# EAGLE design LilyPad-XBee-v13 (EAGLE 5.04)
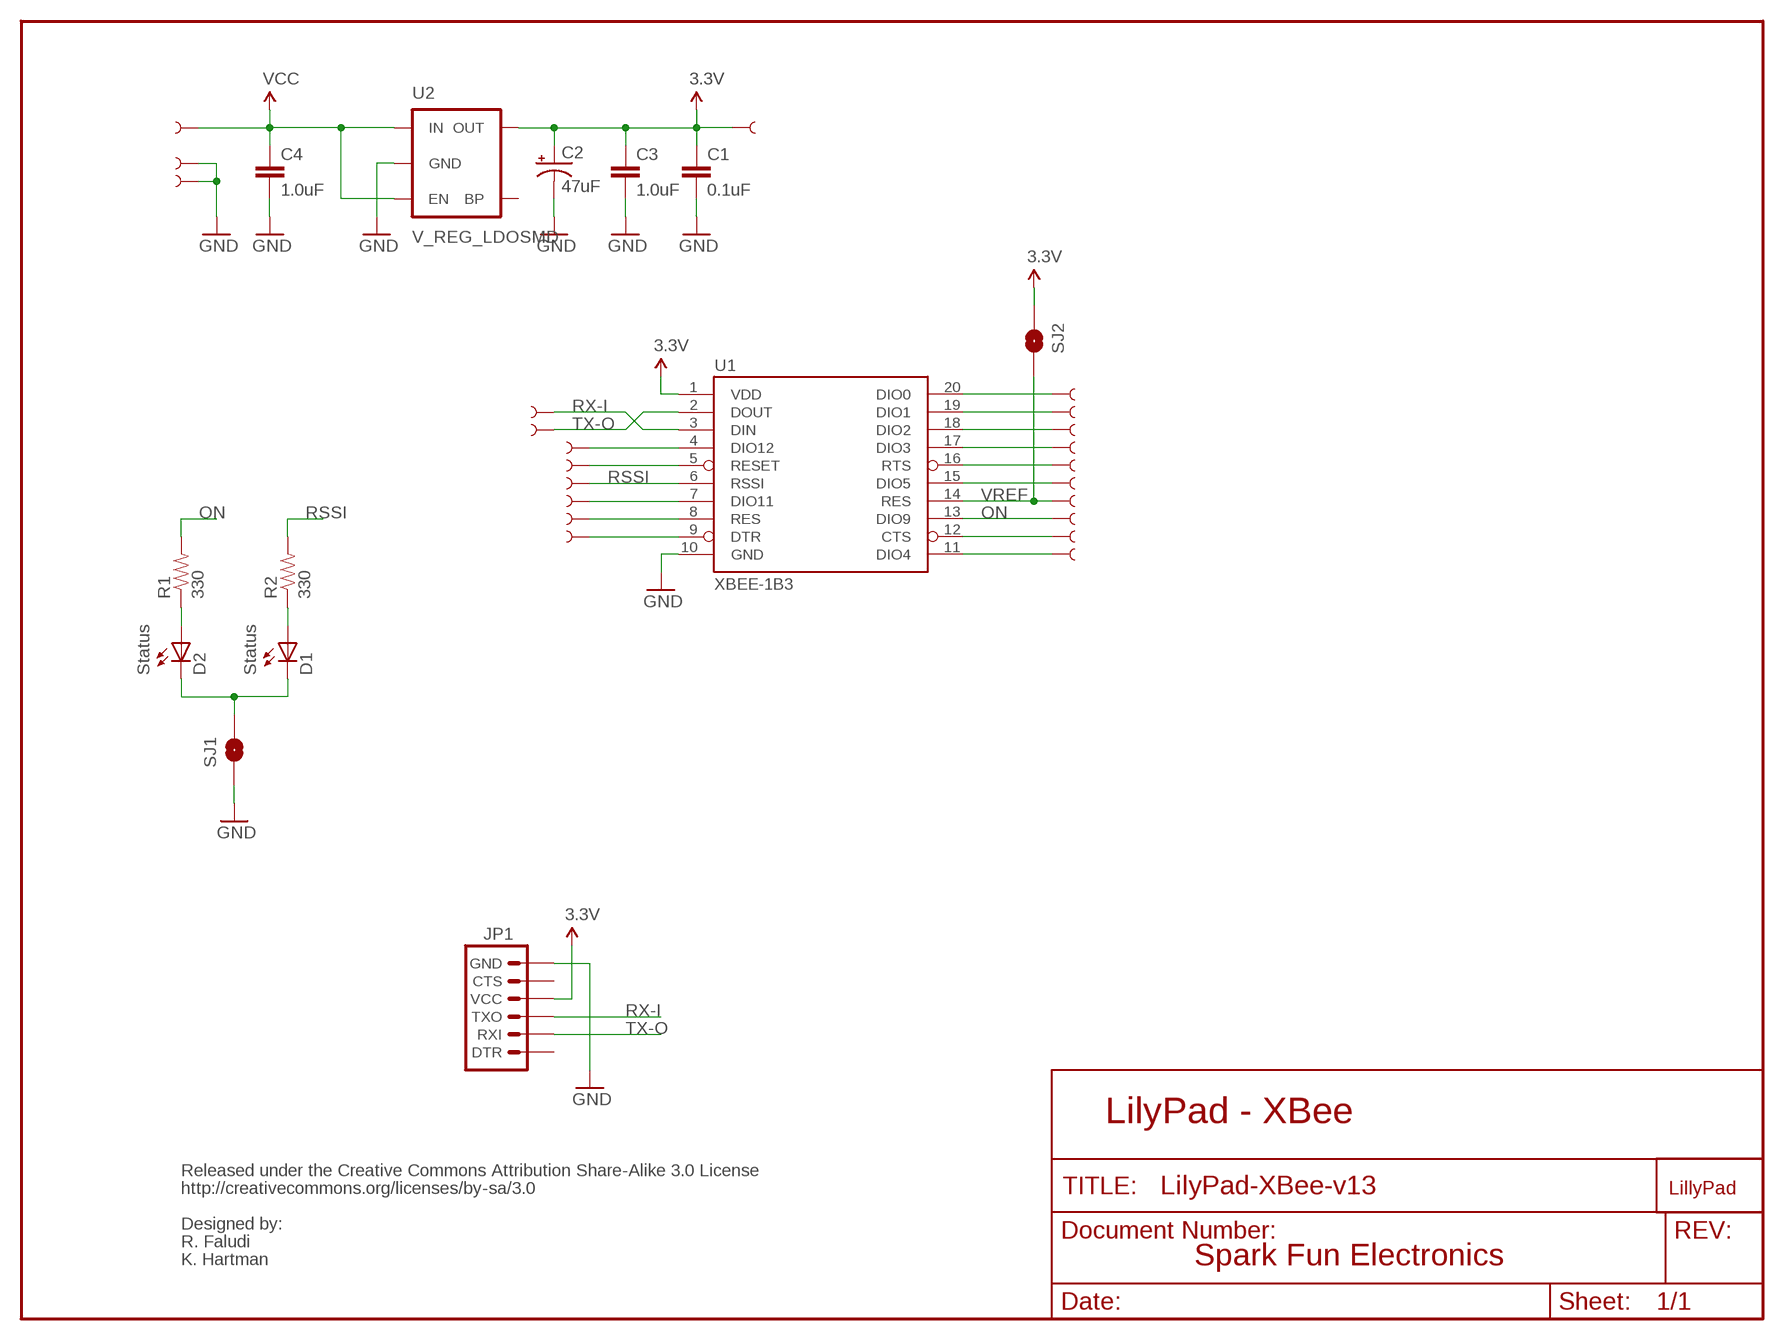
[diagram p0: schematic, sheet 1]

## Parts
C1  0.1uF  CAP0402-CAP  [0402-CAP]
C2  47uF  CAP_POL3528  [EIA3528]
C3  1.0uF  CAP0402-CAP  [0402-CAP]
C4  1.0uF  CAP0402-CAP  [0402-CAP]
D1  Status  LED0603  [LED-0603]
D2  Status  LED0603  [LED-0603]
GND  SEWTAP1  [SEWTAP]
JP1  ARDUINO_SERIAL_PROGRAMPTH  [1X06]
R1  330  RESISTOR0402-RES  [0402-RES]
R2  330  RESISTOR0402-RES  [0402-RES]
SJ1  SOLDERJUMPERNC2  [SJ_2S-NOTRACE]
SJ2  SOLDERJUMPERNC2  [SJ_2S-NOTRACE]
U1  XBEE-1B3  [XBEE-SMD]
U2  V_REG_LDOSMD  [SOT23-5]
U$1  LOGO-LPLP  [LOGO-LILYPAD]
U$4  SEWTAP1  [SEWTAP]
U$30  SEWTAP1  [SEWTAP]
U$31  SEWTAP1  [SEWTAP]
U$32  SEWTAP1  [SEWTAP]
U$33  SEWTAP1  [SEWTAP]
U$34  SEWTAP1  [SEWTAP]
U$35  SEWTAP1  [SEWTAP]
U$36  SEWTAP1  [SEWTAP]
U$37  SEWTAP1  [SEWTAP]
U$38  SEWTAP1  [SEWTAP]
U$39  SEWTAP1  [SEWTAP]
U$40  SEWTAP1  [SEWTAP]
U$41  SEWTAP1  [SEWTAP]
U$42  SEWTAP1  [SEWTAP]
U$43  SEWTAP1  [SEWTAP]
U$44  SEWTAP1  [SEWTAP]
U$45  SEWTAP1  [SEWTAP]
U$46  SEWTAP1  [SEWTAP]
U$47  SEWTAP1  [SEWTAP]
U$48  SEWTAP1  [SEWTAP]
U$51  SEWTAP1  [SEWTAP]

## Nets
3.3V: C1.1 C2.A(+) C3.1 JP1.4(VCC) SJ2.1 U1.1(VDD) U2.5(OUT) U$47.1
GND [VCC]: C1.2 C2.C(-) C3.2 C4.2 JP1.6(GND) SJ1.1 U1.10(GND) U2.2(GND) U$36.1 U$46.1
N$1: D1.A R2.1
N$2: D2.A R1.1
N$3: D1.C D2.C SJ1.2
N$4: U1.4(DIO12) U$43.1
N$5: GND.1 U1.5(RESET)
N$7: U1.7(DIO11) U$42.1
N$8: U1.8(RES) U$41.1
N$9: U1.9(DTR) U$48.1
N$10: U1.15(DIO5) U$4.1
N$11: U1.16(RTS) U$30.1
N$12: U1.11(DIO4) U$37.1
N$13: U1.12(CTS) U$38.1
N$16: U1.17(DIO3) U$31.1
N$17: U1.18(DIO2) U$32.1
N$18: U1.19(DIO1) U$33.1
N$19: U1.20(DIO0) U$34.1
ON: R1.2 U1.13(DIO9) U$39.1
RSSI: R2.2 U1.6(RSSI) U$51.1
RX-I: JP1.3(TXO) U1.3(DIN) U$45.1
TX-O: JP1.2(RXI) U1.2(DOUT) U$44.1
VCC [VCC]: C4.1 U2.1(IN) U2.3(EN) U$35.1
VREF: SJ2.2 U1.14(RES) U$40.1
Unconnected: JP1.1(DTR) JP1.5(CTS) U2.4(BP)

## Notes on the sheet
- LilyPad - XBee
- Released under the Creative Commons Attribution Share-Alike 3.0 License
- http://creativecommons.org/licenses/by-sa/3.0
- Designed by:
- R. Faludi
- K. Hartman | Spark Fun Electronics

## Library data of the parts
C1 C3 C4 = SparkFun:CAP: Capacitor
C2 = SparkFun:CAP_POL: Capacitor Polarized
D1 D2 = SparkFun:LED: LEDs
GND U$4 U$30-U$48 U$51 = LilyPad-Wearables:SEWTAP
JP1 = SparkFun:ARDUINO_SERIAL_PROGRAM
R1 R2 = SparkFun:RESISTOR: Resistor
SJ1 SJ2 = SparkFun:SOLDERJUMPER: Solder Jumper
U1 = SparkFun:XBEE-1
U2 = SparkFun:V_REG_LDO: Voltage Regulator LDO Standard 150mA LDO voltage regulator in SOT-23 layout. Micrel part MIC5205. BP (by-pass) pin is used to lower output noise with 470pF cap.
U$1 = LilyPad-Wearables:LOGO-LP

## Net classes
0 Default: width 0.203 mm
1 VCC: width 0.305 mm

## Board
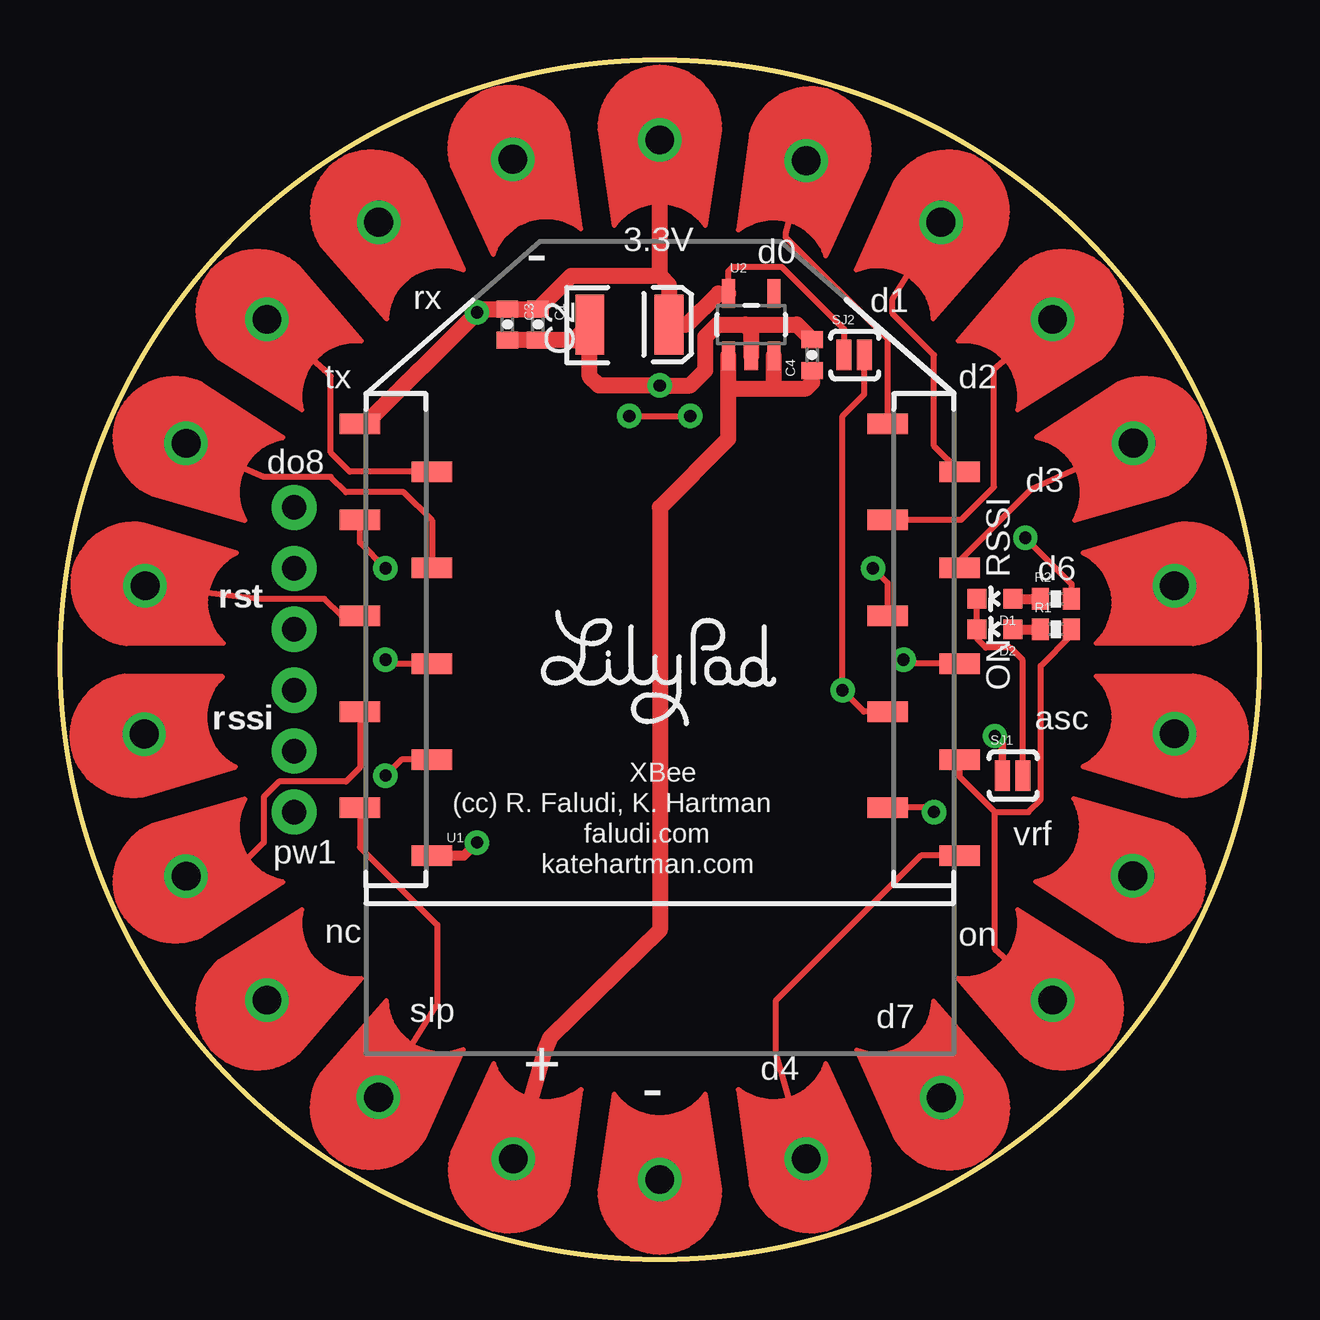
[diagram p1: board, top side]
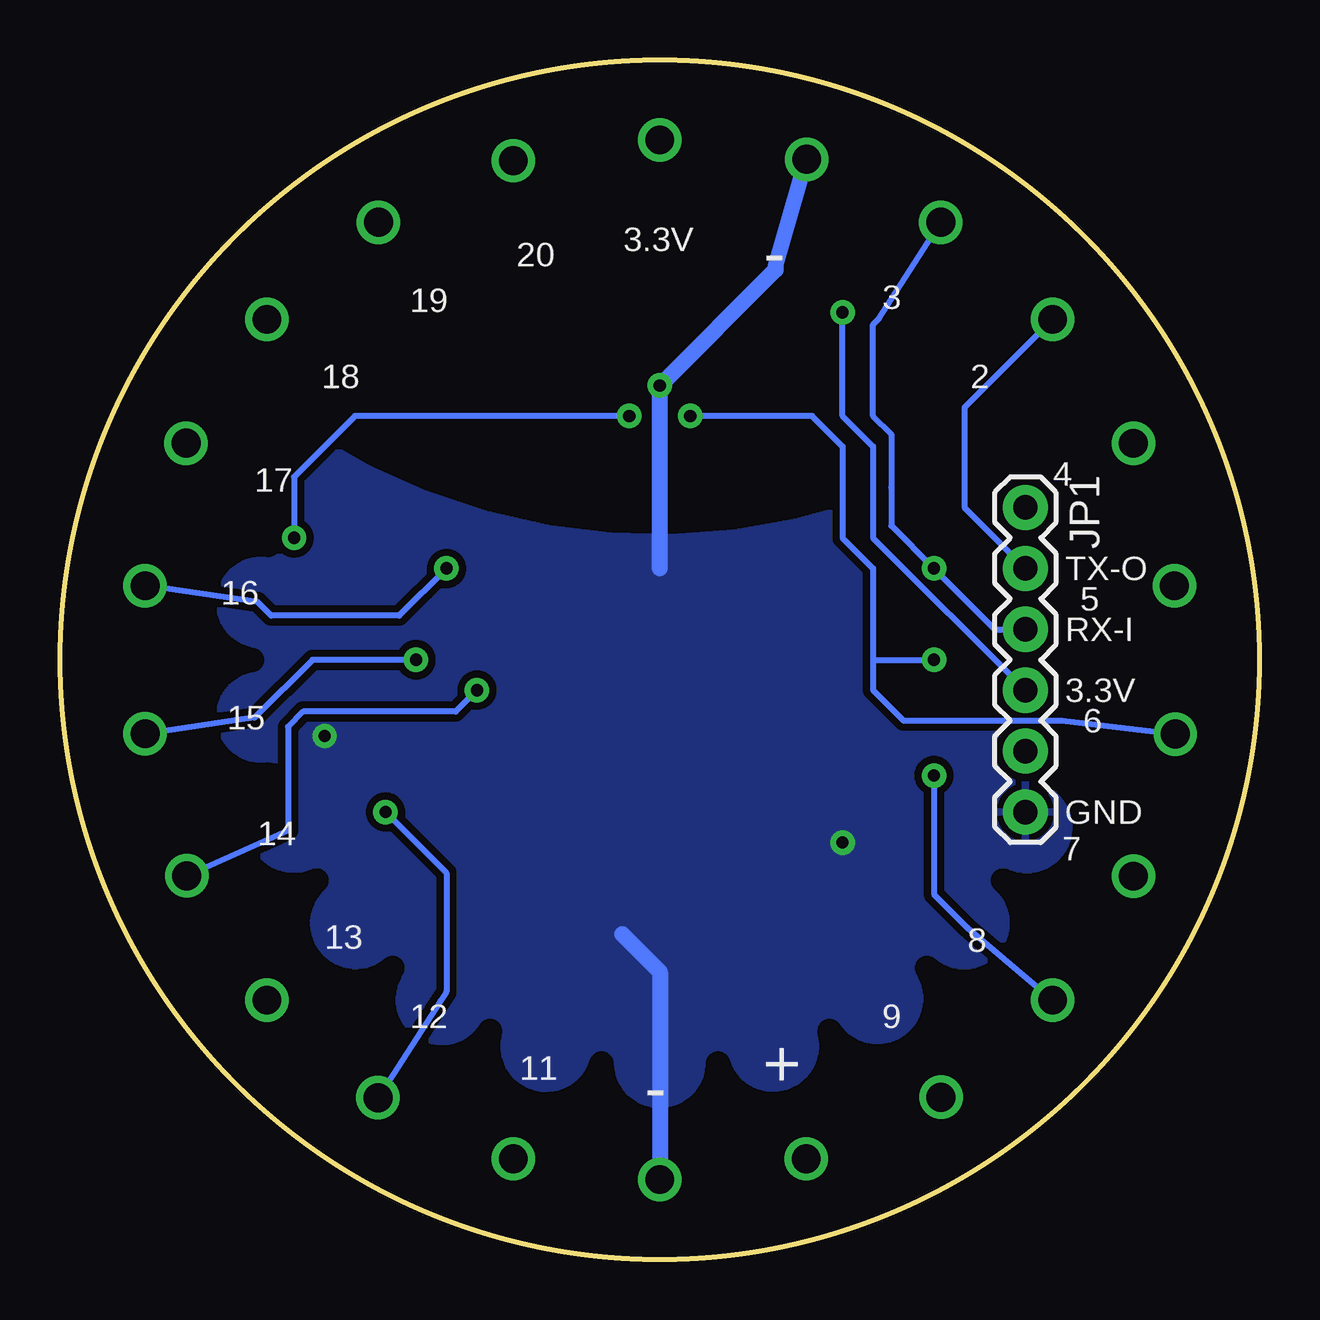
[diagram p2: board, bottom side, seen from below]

Size 50 x 50 mm. Coordinates in mm from the lower left corner, seen from the top.
Outline: circle at 25,25 radius 25
Copper layers (1*16): Top 0.035mm / dielectric 1.5mm / Bottom 0.035mm
Design rules "SparkFun": minimum track width 8mil, minimum drill 20mil, track to track 8mil, track to pad 8mil, pad to pad 8mil, via to via 8mil, smd to smd 8mil, copper to edge 10mil, drill to drill 8mil, minimum pad ring 12mil, minimum via ring 10mil, stop-mask expansion 4mil, vias tented up to drill 20mil, thermal gap 10mil
bRestrict: area 2.4,2.4 to 47.6,47.6; area 21,42.8 to 23.5,44; area 31.6,41.3 to 34.4,43; area 36.3,38.4 to 38.9,40.7; area 40,34.1 to 42,36.9; area 42.2,29.2 to 43.6,31.8; area 42.8,23.9 to 44,26.2; area 42.2,18.2 to 43.7,20.9; area 36.3,9.4 to 39,11.7; area 31.7,7 to 34.5,8.7; area 26.5,6 to 28.9,7.3; area 21.1,6 to 23.6,7.3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; 22 lines

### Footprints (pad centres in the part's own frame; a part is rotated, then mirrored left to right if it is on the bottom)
0402-CAP = smd 0.7 x 0.9: 1 -0.65,0; 2 0.65,0
EIA3528 = smd 1.2 x 2.5: A 1.65,0; C -1.65,0
LED-0603 = smd 0.8 x 0.8: A 0,-0.75; C 0,0.75
SEWTAP = drill 1.2 round: 1 0.03,0
1X06 = drill 1.016 pad 1.88 round: 1 0,0; 2 2.54,0; 3 5.08,0; 4 7.62,0; 5 10.16,0; 6 12.7,0
0402-RES = smd 0.7 x 0.9: 1 -0.65,0; 2 0.65,0
SJ_2S-NOTRACE = smd 0.635 x 1.27: 1 -0.45,0; 2 0.4,0
XBEE-SMD = smd 1.7 x 0.85: 1 -12.5,20; 2 -9.5,18; 3 -12.5,16; 4 -9.5,14; 5 -12.5,12; 6 -9.5,10; 7 -12.5,8; 8 -9.5,6; 9 -12.5,4; 10 -9.5,2; 11 12.5,2; 12 9.5,4; 13 12.5,6; 14 9.5,8; 15 12.5,10; 16 9.5,12; 17 12.5,14; 18 9.5,16; 19 12.5,18; 20 9.5,20
SOT23-5 = smd 0.55 x 1.2: 1 -0.95,-1.3; 2 0,-1.3; 3 0.95,-1.3; 4 0.95,1.3; 5 -0.95,1.3

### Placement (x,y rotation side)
C1  19.92,38.97 270 top
C2  23.73,38.97 0 top
C3  18.65,38.97 270 top
C4  31.35,37.7 90 top
D1  38.97,27.54 90 top
D2  38.97,26.27 90 top
GND  3.52,28.09 351.8 top
JP1  9.76,31.35 270 bottom
R1  41.51,26.27 0 top
R2  41.51,27.54 0 top
SJ1  39.73,20.17 0 top
SJ2  33.13,37.7 0 top
U1  25,14.84 0 top
U2  28.81,38.97 0 top
U$1  25,25 0 top
U$4  46.48,21.91 171.8 top
U$30  46.48,28.09 188.2 top
U$31  44.77,34.04 204.5 top
U$32  41.4,39.21 220.9 top
U$33  36.74,43.26 237.3 top
U$34  31.11,45.83 253.7 top
U$35  18.89,4.17 73.7 top
U$36  25,3.3 90 top
U$37  31.11,4.17 106.3 top
U$38  36.76,6.72 122.7 top
U$39  41.4,10.79 139.1 top
U$40  44.74,15.98 155.5 top
U$41  8.6,10.79 40.9 top
U$42  5.23,15.97 24.5 top
U$43  5.23,34.03 335.5 top
U$44  8.6,39.21 319.1 top
U$45  13.27,43.26 302.7 top
U$46  18.87,45.89 286.3 top
U$47  25,46.7 270 top
U$48  13.26,6.74 57.3 top
U$51  3.48,21.9 8.2 top

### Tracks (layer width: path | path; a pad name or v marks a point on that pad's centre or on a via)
3.3V  (via drill 0.51)
  Top 0.254: U2.5 27.86,41.2 28.05,41.38 30.08,41.38 32.68,38.78 SJ2.1
  Top 0.66: C2.A 25.25,38.97 | 19.92,39.61 C3.1 17.52,39.62 v17.38,39.48 12.74,34.84 U1.1 | U2.5 27.44,40.27 26.14,38.97 C2.A | C2.A 25.38,40.62 25,41 | 19.92,39.61 C1.1 | 25,41 21.32,41 19.92,39.61 | 25,41 U$47.1
  Bottom 0.254: JP1.4 16.11,30.08 16.11,33.89 17.38,35.16 v17.38,39.48
GND  (via drill 0.51)
  Top 0.305: SJ1.1 39.28,21.51 v38.97,21.82
  Top 0.406: U1.10 16.84,16.84 v17.38,17.38
  Top 0.66: C3.2 19.91,38.32 19.92,38.34 C1.2 21.43,38.32 C2.C 22.08,36.81 22.46,36.43 v25,36.43 26.27,36.43 26.91,37.06 26.91,38.46 27.41,38.97 28.56,38.97 | U2.2 28.81,38.72 28.56,38.97 | C4.2 31.35,38.34 30.71,38.97 28.56,38.97
  Bottom 0.66: 25,28.81 v25,36.43 20.17,41.26 20.17,41.38 U$46.1 | U$36.1 25,12 26.57,13.57
  pour Bottom (isolate 0.305): -1,52.27 arc159 51,51 51,-1 -1,-1
N$1
  Top 0.406: D1.A R2.1
N$2
  Top 0.406: D2.A R1.1
N$3
  Top 0.254: D2.C D1.C | D2.C 38.22,26.13 | D2.C 38.22,25.88 38.59,25.51 39.61,25.51 40.13,24.98 SJ1.2
N$4
  Top 0.254: U$43.1 8.49,32.62 11.28,32.62 11.92,31.98 14.33,31.98 15.5,30.82 U1.4
N$5
  Top 0.254: GND.1 8.24,27.54 11.03,27.54 11.73,26.84 U1.5
N$7
  Top 0.254: U1.7 12.5,20.5 11.92,19.92 9.12,19.92 8.49,19.29 8.49,17.38 7.09,15.98 U$42.1
N$8  (via drill 0.51)
  Top 0.254: U1.8 14.24,20.84 v13.57,20.17
  Bottom 0.254: U$41.1 12.17,13.82 13.57,15.22 v13.57,20.17
N$9
  Top 0.254: U$48.1 15.73,10.65 15.73,13.95 12.5,17.18 U1.9
N$10  (via drill 0.51)
  Top 0.254: U1.15 35.32,24.84 v35.16,25
  Bottom 0.254: U$4.1 41.89,22.59 39.48,25 v35.16,25
N$11  (via drill 0.51)
  Top 0.254: U1.16 34.5,28.2 v33.89,28.81
  Bottom 0.254: U$30.1 41.76,27.41 41.19,26.84 35.86,26.84 v33.89,28.81
N$12
  Top 0.254: U$37.1 29.83,8.62 29.83,10.78 35.89,16.84 U1.11
N$13  (via drill 0.51)
  Top 0.254: U1.12 36.24,18.84 v36.43,18.65
  Bottom 0.254: U$38.1 34.14,10.78 33.89,11.16 33.89,16.11 v36.43,18.65
N$16
  Top 0.254: U$31.1 40.49,32.11 37.22,28.84
  Top 0.406: U1.17 37.22,28.84
N$17
  Top 0.254: U$32.1 38.93,37.11 38.93,32.2 37.57,30.84 U1.18
N$18
  Top 0.254: U$33.1 34.7,40.03 34.7,39.43 36.43,37.7 36.43,33.91 U1.19
N$19
  Top 0.254: U$34.1 30.26,42.8 30.26,42.6 34.5,38.36 U1.20
ON
  Top 0.254: U$39.1 38.97,12.94 38.97,18.65 | U1.13 37.5,20.12 38.97,18.65 | R1.2 42.16,26.03 40.88,24.75 40.88,19.16 40.37,18.65 38.97,18.65
RSSI  (via drill 0.51)
  Top 0.254: v23.73,35.16 v26.27,35.16 | U1.6 13.73,24.84 v13.57,25 | R2.2 42.16,28.16 v40.24,30.08
  Bottom 0.254: v40.24,30.08 40.24,32.62 37.7,35.16 v26.27,35.16 | v23.73,35.16 18.65,35.16 17.38,33.89 17.38,30.08 16.11,28.81 16.11,25 | U$51.1 8.24,22.46 14.84,22.46 16.11,23.73 16.11,25 | 16.11,25 v13.57,25
RX-I  (via drill 0.51)
  Top 0.254: U1.3 12.5,29.88 v13.57,28.81
  Bottom 0.254: U$45.1 15.86,39.22 16.11,38.97 16.11,35.16 15.35,34.4 15.35,32.19 15.35,30.59 v13.57,28.81 11.03,26.27 JP1.3
TX-O
  Top 0.254: U$44.1 11.03,37.06 11.28,36.81 11.28,33.64 12.08,32.84 U1.2
  Bottom 0.254: JP1.2 12.3,31.35 12.3,35.51 U$44.1
VCC
  Top 0.66: 27.86,36.3 27.86,34.21 25,31.35 25,13.73 20.43,9.25 20.2,8.7 U$35.1 | 27.86,36.3 U2.1 | 29.76,36.3 U2.3 | C4.1 31.35,36.56 31.1,36.3 29.76,36.3 | 27.86,36.3 29.76,36.3
VREF  (via drill 0.51)
  Top 0.254: U1.14 33.51,22.84 v32.62,23.73 32.62,35.16 33.53,36.07 SJ2.2
  Top 0.406: U1.14 34.78,22.84
  Bottom 0.254: U$40.1 40.49,17.89 40.49,22.21 39.86,22.84 33.51,22.84 v32.62,23.73

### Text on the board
tPlace: 3.3V | d0 | - | rx | d1 | tx | d2 | do8 | d3 | RSSI | d6 | r | s | t | ON | r | s | s | i | asc | XBee | (cc) R. Faludi, K. Hartman | faludi.com | vrf | pw1 | katehartman.com | nc | on | slp | d7 | + | d4 | - | Released under the Creative Commons Attribution Share-Alike 3.0 License | http://creativecommons.org/licenses/by-sa/3.0
bPlace: 3.3V | - | 20 | 3 | 19 | 2 | 18 | 4 | 17 | TX-O | 5 | 16 | RX-I | 3.3V | 6 | 15 | GND | 7 | 14 | 8 | 13 | 9 | 12 | + | 11 | -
